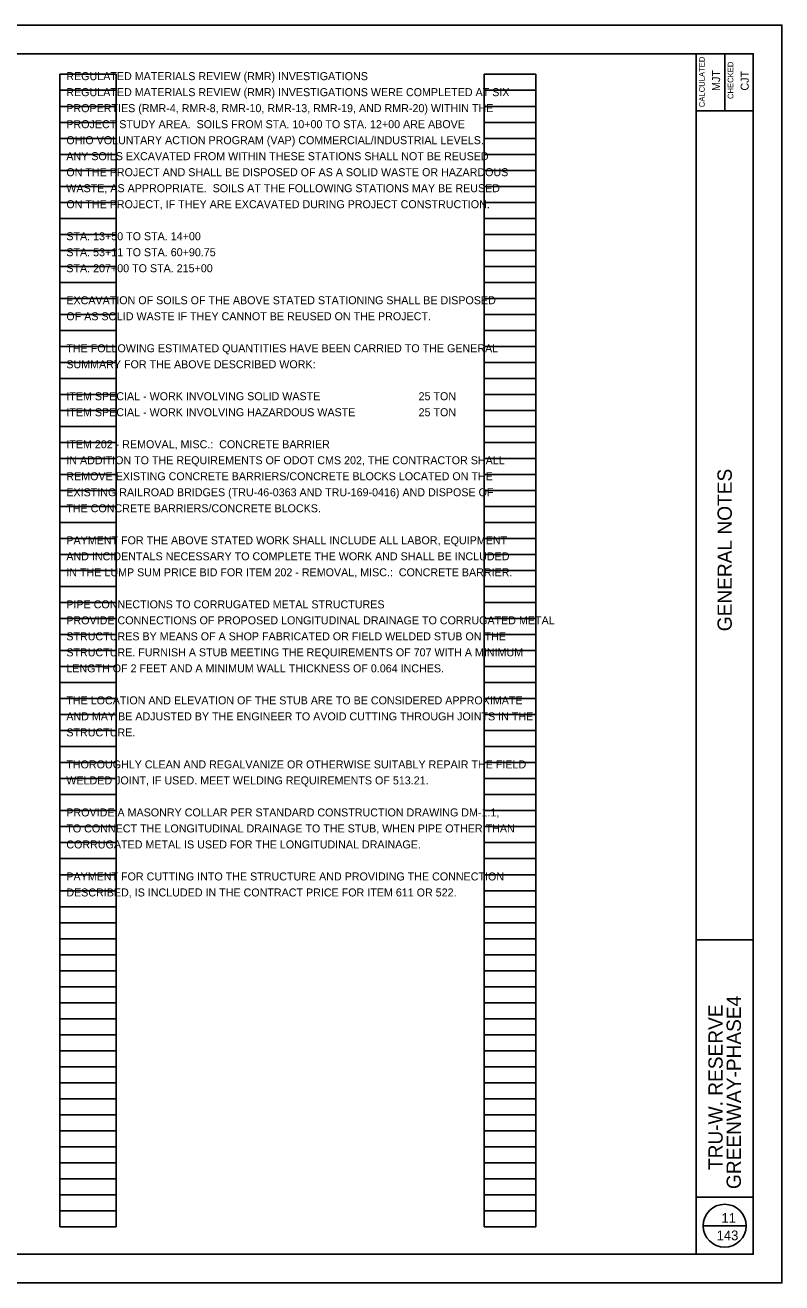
# Model space of a CAD drawing. Extents: x -16 to 195, y -13 to 9.
# Drawn here: x 92.86 to 106.09, y -12.91 to 9.09 of the extents above; entities that cross this region are included whole.
import ezdxf

# ---------------------------------------------------------------- set-up
doc = ezdxf.new("R2010")
doc.units = 0
for name, color, linetype in [('SH_Border', 7, 'Continuous'), ('SH_Cut_Line', 7, 'Continuous'), ('SH_Data', 7, 'Continuous'), ('TX_P_1', 7, 'Continuous')]:
    doc.layers.add(name, color=color, linetype=linetype)

msp = doc.modelspace()

# ---------------------------------------------------------------- linework, layer by layer
at = {"layer": 'SH_Border'}
for p, q in [((104.594, -12.407), (104.594, 8.593)), ((105.094, 8.593), (105.094, 7.593)), ((104.594, 7.593), (105.594, 7.593)), ((104.594, -6.907), (105.594, -6.907)), ((104.594, -11.407), (105.594, -11.407))]:
    msp.add_line(p, q, dxfattribs=at)
msp.add_lwpolyline([(74.094, 8.593), (105.594, 8.593), (105.594, -12.407), (74.094, -12.407)], close=True, dxfattribs=at)
at = {"layer": 'SH_Cut_Line'}
msp.add_lwpolyline([(72.094, -12.907), (106.094, -12.907), (106.094, 9.093), (72.094, 9.093)], close=True, dxfattribs=at)
at = {"layer": 'SH_Data'}
for p, q in [((93.47, -11.927), (93.47, 8.233)), ((93.47, 8.233), (94.45, 8.233)), ((94.45, -11.927), (94.45, 8.233)), ((100.89, -11.927), (100.89, 8.233)), ((100.89, 8.233), (101.79, 8.233)), ((101.79, -11.927), (101.79, 8.233)), ((93.47, 7.953), (94.45, 7.953)), ((100.89, 7.953), (101.79, 7.953)), ((93.47, 7.673), (94.45, 7.673)), ((100.89, 7.673), (101.79, 7.673)), ((93.47, 7.393), (94.45, 7.393)), ((100.89, 7.393), (101.79, 7.393)), ((93.47, 7.113), (94.45, 7.113)), ((100.89, 7.113), (101.79, 7.113)), ((93.47, 6.833), (94.45, 6.833)), ((100.89, 6.833), (101.79, 6.833)), ((93.47, 6.553), (94.45, 6.553)), ((100.89, 6.553), (101.79, 6.553)), ((93.47, 6.273), (94.45, 6.273)), ((100.89, 6.273), (101.79, 6.273)), ((93.47, 5.993), (94.45, 5.993)), ((100.89, 5.993), (101.79, 5.993)), ((93.47, 5.713), (94.45, 5.713)), ((100.89, 5.713), (101.79, 5.713)), ((93.47, 5.433), (94.45, 5.433)), ((100.89, 5.433), (101.79, 5.433)), ((93.47, 5.153), (94.45, 5.153)), ((100.89, 5.153), (101.79, 5.153)), ((93.47, 4.873), (94.45, 4.873)), ((100.89, 4.873), (101.79, 4.873)), ((93.47, 4.593), (94.45, 4.593)), ((100.89, 4.593), (101.79, 4.593)), ((93.47, 4.313), (94.45, 4.313)), ((100.89, 4.313), (101.79, 4.313)), ((93.47, 4.033), (94.45, 4.033)), ((100.89, 4.033), (101.79, 4.033)), ((93.47, 3.753), (94.45, 3.753)), ((100.89, 3.753), (101.79, 3.753)), ((93.47, 3.473), (94.45, 3.473)), ((100.89, 3.473), (101.79, 3.473)), ((93.47, 3.193), (94.45, 3.193)), ((100.89, 3.193), (101.79, 3.193)), ((93.47, 2.913), (94.45, 2.913)), ((100.89, 2.913), (101.79, 2.913)), ((93.47, 2.633), (94.45, 2.633)), ((100.89, 2.633), (101.79, 2.633)), ((93.47, 2.353), (94.45, 2.353)), ((100.89, 2.353), (101.79, 2.353)), ((93.47, 2.073), (94.45, 2.073)), ((100.89, 2.073), (101.79, 2.073)), ((93.47, 1.793), (94.45, 1.793)), ((100.89, 1.793), (101.79, 1.793)), ((93.47, 1.513), (94.45, 1.513)), ((100.89, 1.513), (101.79, 1.513)), ((93.47, 1.233), (94.45, 1.233)), ((100.89, 1.233), (101.79, 1.233)), ((93.47, 0.953), (94.45, 0.953)), ((100.89, 0.953), (101.79, 0.953)), ((93.47, 0.673), (94.45, 0.673)), ((100.89, 0.673), (101.79, 0.673)), ((93.47, 0.393), (94.45, 0.393)), ((100.89, 0.393), (101.79, 0.393)), ((93.47, 0.113), (94.45, 0.113)), ((100.89, 0.113), (101.79, 0.113)), ((93.47, -0.167), (94.45, -0.167)), ((100.89, -0.167), (101.79, -0.167)), ((93.47, -0.447), (94.45, -0.447)), ((100.89, -0.447), (101.79, -0.447)), ((93.47, -0.727), (94.45, -0.727)), ((100.89, -0.727), (101.79, -0.727)), ((93.47, -1.007), (94.45, -1.007)), ((100.89, -1.007), (101.79, -1.007)), ((93.47, -1.287), (94.45, -1.287)), ((100.89, -1.287), (101.79, -1.287)), ((93.47, -1.567), (94.45, -1.567)), ((100.89, -1.567), (101.79, -1.567)), ((93.47, -1.847), (94.45, -1.847)), ((100.89, -1.847), (101.79, -1.847)), ((93.47, -2.127), (94.45, -2.127)), ((100.89, -2.127), (101.79, -2.127)), ((93.47, -2.407), (94.45, -2.407)), ((100.89, -2.407), (101.79, -2.407)), ((93.47, -2.687), (94.45, -2.687)), ((100.89, -2.687), (101.79, -2.687)), ((93.47, -2.967), (94.45, -2.967)), ((100.89, -2.967), (101.79, -2.967)), ((93.47, -3.247), (94.45, -3.247)), ((100.89, -3.247), (101.79, -3.247)), ((93.47, -3.527), (94.45, -3.527)), ((100.89, -3.527), (101.79, -3.527)), ((93.47, -3.807), (94.45, -3.807)), ((100.89, -3.807), (101.79, -3.807)), ((93.47, -4.087), (94.45, -4.087)), ((100.89, -4.087), (101.79, -4.087)), ((93.47, -4.367), (94.45, -4.367)), ((100.89, -4.367), (101.79, -4.367)), ((93.47, -4.647), (94.45, -4.647)), ((100.89, -4.647), (101.79, -4.647)), ((93.47, -4.927), (94.45, -4.927)), ((100.89, -4.927), (101.79, -4.927)), ((93.47, -5.207), (94.45, -5.207)), ((100.89, -5.207), (101.79, -5.207)), ((93.47, -5.487), (94.45, -5.487)), ((100.89, -5.487), (101.79, -5.487)), ((93.47, -5.767), (94.45, -5.767)), ((100.89, -5.767), (101.79, -5.767)), ((93.47, -6.047), (94.45, -6.047)), ((100.89, -6.047), (101.79, -6.047)), ((93.47, -6.327), (94.45, -6.327)), ((100.89, -6.327), (101.79, -6.327)), ((93.47, -6.607), (94.45, -6.607)), ((100.89, -6.607), (101.79, -6.607)), ((93.47, -6.887), (94.45, -6.887)), ((100.89, -6.887), (101.79, -6.887)), ((93.47, -7.167), (94.45, -7.167)), ((100.89, -7.167), (101.79, -7.167)), ((93.47, -7.447), (94.45, -7.447)), ((100.89, -7.447), (101.79, -7.447)), ((93.47, -7.727), (94.45, -7.727)), ((100.89, -7.727), (101.79, -7.727)), ((93.47, -8.007), (94.45, -8.007)), ((100.89, -8.007), (101.79, -8.007)), ((93.47, -8.287), (94.45, -8.287)), ((100.89, -8.287), (101.79, -8.287)), ((93.47, -8.567), (94.45, -8.567)), ((100.89, -8.567), (101.79, -8.567)), ((93.47, -8.847), (94.45, -8.847)), ((100.89, -8.847), (101.79, -8.847)), ((93.47, -9.127), (94.45, -9.127)), ((100.89, -9.127), (101.79, -9.127)), ((93.47, -9.407), (94.45, -9.407)), ((100.89, -9.407), (101.79, -9.407)), ((93.47, -9.687), (94.45, -9.687)), ((100.89, -9.687), (101.79, -9.687)), ((93.47, -9.967), (94.45, -9.967)), ((100.89, -9.967), (101.79, -9.967)), ((93.47, -10.247), (94.45, -10.247)), ((100.89, -10.247), (101.79, -10.247)), ((93.47, -10.527), (94.45, -10.527)), ((100.89, -10.527), (101.79, -10.527)), ((93.47, -10.807), (94.45, -10.807)), ((100.89, -10.807), (101.79, -10.807)), ((93.47, -11.087), (94.45, -11.087)), ((100.89, -11.087), (101.79, -11.087)), ((93.47, -11.367), (94.45, -11.367)), ((100.89, -11.367), (101.79, -11.367)), ((93.47, -11.647), (94.45, -11.647)), ((100.89, -11.647), (101.79, -11.647)), ((93.47, -11.927), (94.45, -11.927)), ((100.89, -11.927), (101.79, -11.927)), ((104.719, -11.907), (105.469, -11.907))]:
    msp.add_line(p, q, dxfattribs=at)
msp.add_circle((105.094, -11.907), 0.375, dxfattribs=at)

# ---------------------------------------------------------------- texts
for s, height, p in [('CALCULATED', 0.1, (104.746, 7.658)), ('CHECKED', 0.1, (105.246, 7.801)), ('MJT', 0.14, (105.014, 7.942)), ('CJT', 0.14, (105.514, 7.949)), ('GENERAL NOTES', 0.25, (105.219, -1.509)), ('GREENWAY-PHASE4', 0.25, (105.378, -11.266)), ('TRU-W. RESERVE', 0.25, (105.059, -10.934))]:
    msp.add_text(s, height=height, rotation=90, dxfattribs=at).set_placement(p)
for s, p in [('11', (105.038, -11.857)), ('143', (104.954, -12.162))]:
    msp.add_text(s, height=0.17, dxfattribs=at).set_placement(p)
at = {"layer": 'TX_P_1'}
for s, p in [('REGULATED MATERIALS REVIEW (RMR) INVESTIGATIONS', (93.581, 8.131)), ('REGULATED MATERIALS REVIEW (RMR) INVESTIGATIONS WERE COMPLETED AT SIX', (93.581, 7.851)), ('PROPERTIES (RMR-4, RMR-8, RMR-10, RMR-13, RMR-19, AND RMR-20) WITHIN THE', (93.581, 7.571)), ('PROJECT STUDY AREA.  SOILS FROM STA. 10+00 TO STA. 12+00 ARE ABOVE', (93.581, 7.291)), ('OHIO VOLUNTARY ACTION PROGRAM (VAP) COMMERCIAL/INDUSTRIAL LEVELS.', (93.581, 7.011)), ('ANY SOILS EXCAVATED FROM WITHIN THESE STATIONS SHALL NOT BE REUSED', (93.581, 6.731)), ('ON THE PROJECT AND SHALL BE DISPOSED OF AS A SOLID WASTE OR HAZARDOUS', (93.581, 6.451)), ('WASTE, AS APPROPRIATE.  SOILS AT THE FOLLOWING STATIONS MAY BE REUSED', (93.581, 6.171)), ('ON THE PROJECT, IF THEY ARE EXCAVATED DURING PROJECT CONSTRUCTION:', (93.581, 5.891)), ('STA. 13+50 TO STA. 14+00', (93.581, 5.331)), ('STA. 53+11 TO STA. 60+90.75', (93.581, 5.051)), ('STA. 207+00 TO STA. 215+00', (93.581, 4.771)), ('EXCAVATION OF SOILS OF THE ABOVE STATED STATIONING SHALL BE DISPOSED', (93.581, 4.211)), ('OF AS SOLID WASTE IF THEY CANNOT BE REUSED ON THE PROJECT.', (93.581, 3.931)), ('THE FOLLOWING ESTIMATED QUANTITIES HAVE BEEN CARRIED TO THE GENERAL', (93.581, 3.371)), ('SUMMARY FOR THE ABOVE DESCRIBED WORK:', (93.581, 3.091)), ('ITEM SPECIAL - WORK INVOLVING SOLID WASTE', (93.581, 2.532)), ('25 TON', (99.741, 2.532)), ('ITEM SPECIAL - WORK INVOLVING HAZARDOUS WASTE', (93.581, 2.252)), ('25 TON', (99.741, 2.252)), ('ITEM 202 - REMOVAL, MISC.:  CONCRETE BARRIER', (93.581, 1.692)), ('IN ADDITION TO THE REQUIREMENTS OF ODOT CMS 202, THE CONTRACTOR SHALL', (93.581, 1.412)), ('REMOVE EXISTING CONCRETE BARRIERS/CONCRETE BLOCKS LOCATED ON THE', (93.581, 1.132)), ('EXISTING RAILROAD BRIDGES (TRU-46-0363 AND TRU-169-0416) AND DISPOSE OF', (93.581, 0.852)), ('THE CONCRETE BARRIERS/CONCRETE BLOCKS. ', (93.581, 0.572)), ('PAYMENT FOR THE ABOVE STATED WORK SHALL INCLUDE ALL LABOR, EQUIPMENT', (93.581, 0.012)), ('AND INCIDENTALS NECESSARY TO COMPLETE THE WORK AND SHALL BE INCLUDED ', (93.581, -0.268)), ('IN THE LUMP SUM PRICE BID FOR ITEM 202 - REMOVAL, MISC.:  CONCRETE BARRIER.', (93.581, -0.548)), ('PIPE CONNECTIONS TO CORRUGATED METAL STRUCTURES', (93.581, -1.108)), ('PROVIDE CONNECTIONS OF PROPOSED LONGITUDINAL DRAINAGE TO CORRUGATED METAL', (93.581, -1.388)), ('STRUCTURES BY MEANS OF A SHOP FABRICATED OR FIELD WELDED STUB ON THE', (93.581, -1.668)), ('STRUCTURE. FURNISH A STUB MEETING THE REQUIREMENTS OF 707 WITH A MINIMUM', (93.581, -1.948)), ('LENGTH OF 2 FEET AND A MINIMUM WALL THICKNESS OF 0.064 INCHES.', (93.581, -2.228)), ('THE LOCATION AND ELEVATION OF THE STUB ARE TO BE CONSIDERED APPROXIMATE', (93.581, -2.788)), ('AND MAY BE ADJUSTED BY THE ENGINEER TO AVOID CUTTING THROUGH JOINTS IN THE', (93.581, -3.068)), ('STRUCTURE.', (93.581, -3.348)), ('THOROUGHLY CLEAN AND REGALVANIZE OR OTHERWISE SUITABLY REPAIR THE FIELD', (93.581, -3.908)), ('WELDED JOINT, IF USED. MEET WELDING REQUIREMENTS OF 513.21.', (93.581, -4.188)), ('PROVIDE A MASONRY COLLAR PER STANDARD CONSTRUCTION DRAWING DM-1.1, ', (93.581, -4.748)), ('TO CONNECT THE LONGITUDINAL DRAINAGE TO THE STUB, WHEN PIPE OTHER THAN', (93.581, -5.028)), ('CORRUGATED METAL IS USED FOR THE LONGITUDINAL DRAINAGE.', (93.581, -5.308)), ('PAYMENT FOR CUTTING INTO THE STRUCTURE AND PROVIDING THE CONNECTION', (93.581, -5.868)), ('DESCRIBED, IS INCLUDED IN THE CONTRACT PRICE FOR ITEM 611 OR 522.', (93.581, -6.148))]:
    msp.add_text(s, height=0.14, dxfattribs=at).set_placement(p)

doc.saveas('drawing.dxf')
